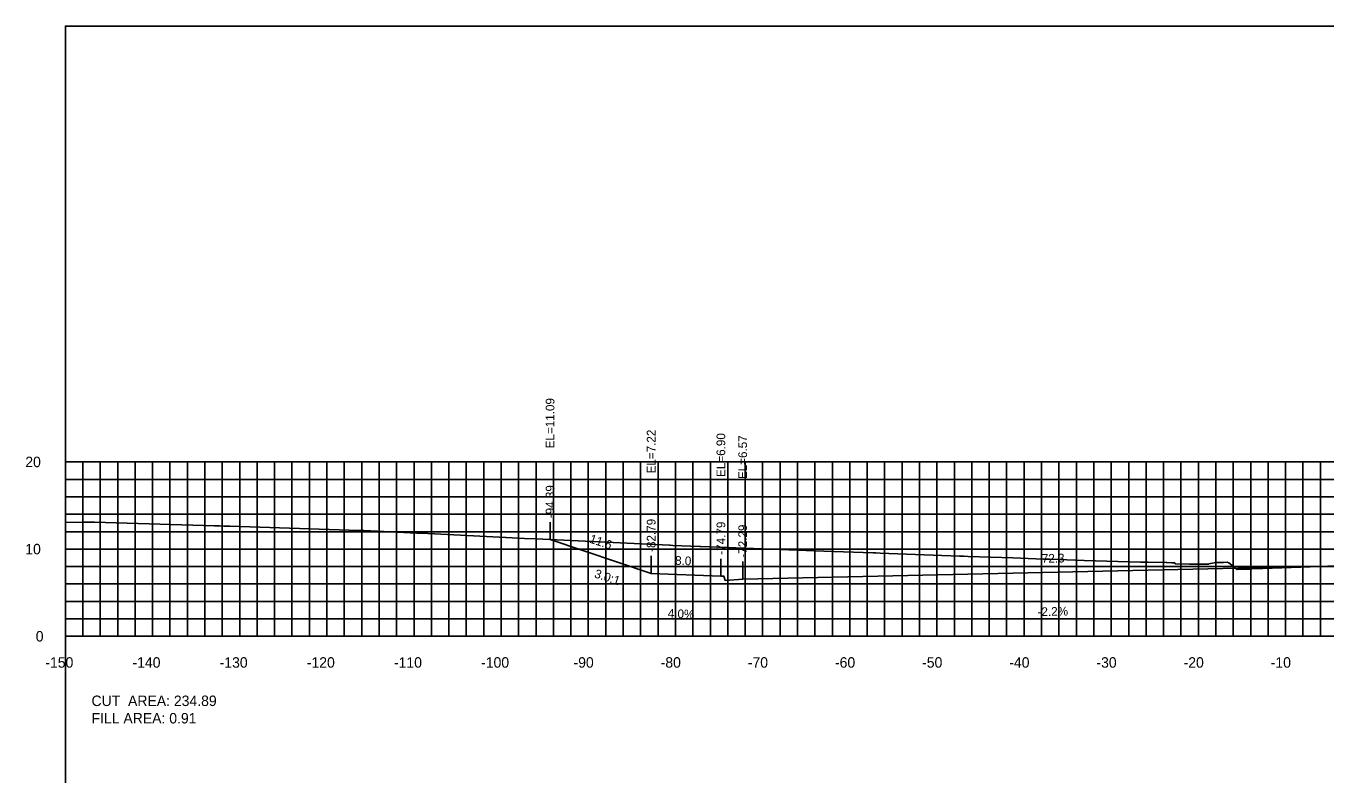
# Model space of a CAD drawing. Extents: x 1797419 to 1809236, y 248759 to 251512.
# Drawn here: x 1804856.5 to 1805005.6, y 250959 to 251044.9 of the extents above; entities that cross this region are included whole.
import ezdxf

# ---------------------------------------------------------------- set-up
doc = ezdxf.new("R2010")
doc.units = 0
for name, color, linetype in [('10', 7, 'Continuous'), ('3', 7, 'Continuous'), ('31', 7, 'Continuous'), ('4', 7, 'Continuous'), ('60', 7, 'Continuous'), ('ANNO-TXT', 7, 'Continuous'), ('CL-CNST', 7, 'Continuous'), ('Level 62', 7, 'Continuous'), ('M-ROADS', 7, 'Continuous')]:
    doc.layers.add(name, color=color, linetype=linetype)

msp = doc.modelspace()

# ---------------------------------------------------------------- linework, layer by layer
for p, q in [((1804916.61, 250985.98), (1804916.61, 250987.98)), ((1804928.21, 250982.11), (1804928.21, 250984.11)), ((1804936.21, 250981.79), (1804936.21, 250983.79)), ((1804938.71, 250981.46), (1804938.71, 250983.46))]:
    msp.add_line(p, q)
msp.add_lwpolyline([(1804861, 250854.89), (1805161, 250854.89), (1805161, 251044.89), (1804861, 251044.89)], close=True)
at = {"layer": '60'}
for p, q in [((1804860.94, 250994.89), (1804861, 250994.89)), ((1804861, 250974.89), (1804861, 250994.89)), ((1804860.94, 250984.89), (1804861, 250984.89)), ((1804860.94, 250974.89), (1804861, 250974.89)), ((1804861, 250974.89), (1805161, 250974.89)), ((1804861, 250974.83), (1804861, 250974.89)), ((1804871, 250974.83), (1804871, 250974.89)), ((1804881, 250974.83), (1804881, 250974.89)), ((1804891, 250974.83), (1804891, 250974.89)), ((1804901, 250974.83), (1804901, 250974.89)), ((1804911, 250974.83), (1804911, 250974.89)), ((1804921, 250974.83), (1804921, 250974.89)), ((1804931, 250974.83), (1804931, 250974.89)), ((1804941, 250974.83), (1804941, 250974.89)), ((1804951, 250974.83), (1804951, 250974.89)), ((1804961, 250974.83), (1804961, 250974.89)), ((1804971, 250974.83), (1804971, 250974.89)), ((1804981, 250974.83), (1804981, 250974.89)), ((1804991, 250974.83), (1804991, 250974.89)), ((1805001, 250974.83), (1805001, 250974.89))]:
    msp.add_line(p, q, dxfattribs=at)
at = {"layer": 'CL-CNST'}
msp.add_lwpolyline([(1804916.61, 250985.98), (1804928.21, 250982.11), (1804936.21, 250981.79), (1804936.54, 250981.79), (1804936.71, 250981.29), (1804938.71, 250981.46), (1805011, 250983.05), (1805081, 250981.53), (1805083, 250981.36), (1805083.17, 250981.86), (1805083.5, 250981.86), (1805085.5, 250981.94), (1805090.5, 250982.04), (1805091.5, 250982.08), (1805094.63, 250983.12)], dxfattribs=at)
at = {"layer": 'Level 62'}
for p, q in [((1804861, 250994.89), (1805161, 250994.89)), ((1804861, 250974.89), (1804861, 250994.89)), ((1804863, 250974.89), (1804863, 250994.89)), ((1804865, 250974.89), (1804865, 250994.89)), ((1804867, 250974.89), (1804867, 250994.89)), ((1804869, 250974.89), (1804869, 250994.89)), ((1804871, 250974.89), (1804871, 250994.89)), ((1804873, 250974.89), (1804873, 250994.89)), ((1804875, 250974.89), (1804875, 250994.89)), ((1804877, 250974.89), (1804877, 250994.89)), ((1804879, 250974.89), (1804879, 250994.89)), ((1804881, 250974.89), (1804881, 250994.89)), ((1804883, 250974.89), (1804883, 250994.89)), ((1804885, 250974.89), (1804885, 250994.89)), ((1804887, 250974.89), (1804887, 250994.89)), ((1804889, 250974.89), (1804889, 250994.89)), ((1804891, 250974.89), (1804891, 250994.89)), ((1804893, 250974.89), (1804893, 250994.89)), ((1804895, 250974.89), (1804895, 250994.89)), ((1804897, 250974.89), (1804897, 250994.89)), ((1804899, 250974.89), (1804899, 250994.89)), ((1804901, 250974.89), (1804901, 250994.89)), ((1804903, 250974.89), (1804903, 250994.89)), ((1804905, 250974.89), (1804905, 250994.89)), ((1804907, 250974.89), (1804907, 250994.89)), ((1804909, 250974.89), (1804909, 250994.89)), ((1804911, 250974.89), (1804911, 250994.89)), ((1804913, 250974.89), (1804913, 250994.89)), ((1804915, 250974.89), (1804915, 250994.89)), ((1804917, 250974.89), (1804917, 250994.89)), ((1804919, 250974.89), (1804919, 250994.89)), ((1804921, 250974.89), (1804921, 250994.89)), ((1804923, 250974.89), (1804923, 250994.89)), ((1804925, 250974.89), (1804925, 250994.89)), ((1804927, 250974.89), (1804927, 250994.89)), ((1804929, 250974.89), (1804929, 250994.89)), ((1804931, 250974.89), (1804931, 250994.89)), ((1804933, 250974.89), (1804933, 250994.89)), ((1804935, 250974.89), (1804935, 250994.89)), ((1804937, 250974.89), (1804937, 250994.89)), ((1804939, 250974.89), (1804939, 250994.89)), ((1804941, 250974.89), (1804941, 250994.89)), ((1804943, 250974.89), (1804943, 250994.89)), ((1804945, 250974.89), (1804945, 250994.89)), ((1804947, 250974.89), (1804947, 250994.89)), ((1804949, 250974.89), (1804949, 250994.89)), ((1804951, 250974.89), (1804951, 250994.89)), ((1804953, 250974.89), (1804953, 250994.89)), ((1804955, 250974.89), (1804955, 250994.89)), ((1804957, 250974.89), (1804957, 250994.89)), ((1804959, 250974.89), (1804959, 250994.89)), ((1804961, 250974.89), (1804961, 250994.89)), ((1804963, 250974.89), (1804963, 250994.89)), ((1804965, 250974.89), (1804965, 250994.89)), ((1804967, 250974.89), (1804967, 250994.89)), ((1804969, 250974.89), (1804969, 250994.89)), ((1804971, 250974.89), (1804971, 250994.89)), ((1804973, 250974.89), (1804973, 250994.89)), ((1804975, 250974.89), (1804975, 250994.89)), ((1804977, 250974.89), (1804977, 250994.89)), ((1804979, 250974.89), (1804979, 250994.89)), ((1804981, 250974.89), (1804981, 250994.89)), ((1804983, 250974.89), (1804983, 250994.89)), ((1804985, 250974.89), (1804985, 250994.89)), ((1804987, 250974.89), (1804987, 250994.89)), ((1804989, 250974.89), (1804989, 250994.89)), ((1804991, 250974.89), (1804991, 250994.89)), ((1804993, 250974.89), (1804993, 250994.89)), ((1804995, 250974.89), (1804995, 250994.89)), ((1804997, 250974.89), (1804997, 250994.89)), ((1804999, 250974.89), (1804999, 250994.89)), ((1805001, 250974.89), (1805001, 250994.89)), ((1805003, 250974.89), (1805003, 250994.89)), ((1805005, 250974.89), (1805005, 250994.89)), ((1804861, 250992.89), (1805161, 250992.89)), ((1804861, 250990.89), (1805161, 250990.89)), ((1804861, 250988.89), (1805161, 250988.89)), ((1804861, 250986.89), (1805161, 250986.89)), ((1804861, 250984.89), (1805161, 250984.89)), ((1804861, 250982.89), (1805161, 250982.89)), ((1804861, 250980.89), (1805161, 250980.89)), ((1804861, 250978.89), (1805161, 250978.89)), ((1804861, 250976.89), (1805161, 250976.89)), ((1804861, 250974.89), (1805161, 250974.89))]:
    msp.add_line(p, q, dxfattribs=at)
at = {"layer": 'M-ROADS'}
msp.add_lwpolyline([(1804861, 250987.94), (1804862.94, 250987.99), (1804863.07, 250987.99), (1804863.07, 250987.99), (1804863.08, 250987.99), (1804863.37, 250987.99), (1804863.42, 250987.99), (1804863.76, 250987.99), (1804864.1, 250987.98), (1804864.35, 250987.97), (1804878.12, 250987.57), (1804878.67, 250987.56), (1804878.68, 250987.56), (1804879.18, 250987.54), (1804879.83, 250987.52), (1804879.9, 250987.52), (1804894.66, 250987.02), (1804895.19, 250987.01), (1804895.26, 250987.01), (1804896.04, 250986.99), (1804901.32, 250986.73), (1804902.58, 250986.67), (1804903.36, 250986.64), (1804911.53, 250986.22), (1804911.59, 250986.22), (1804913.68, 250986.12), (1804914.99, 250986.05), (1804930.33, 250985.33), (1804930.38, 250985.33), (1804930.69, 250985.32), (1804933.79, 250985.18), (1804933.92, 250985.18), (1804948.01, 250984.67), (1804953.68, 250984.46), (1804953.98, 250984.45), (1804954.47, 250984.44), (1804963.6, 250984.08), (1804964.09, 250984.07), (1804964.57, 250984.06), (1804969.7, 250983.89), (1804973.23, 250983.73), (1804973.52, 250983.73), (1804973.92, 250983.72), (1804977.89, 250983.59), (1804984.34, 250983.41), (1804984.63, 250983.4), (1804985.22, 250983.4), (1804987.31, 250983.36), (1804987.36, 250983.36), (1804987.97, 250983.33), (1804988.29, 250983.32), (1804988.35, 250983.21), (1804989.98, 250983.18), (1804992.17, 250983.16), (1804992.21, 250983.2), (1804992.82, 250983.32), (1804993.08, 250983.35), (1804993.31, 250983.35), (1804993.43, 250983.35), (1804993.65, 250983.35), (1804993.79, 250983.35), (1804993.86, 250983.35), (1804994.3, 250983.39), (1804994.48, 250983.32), (1804994.83, 250983.06), (1804995.09, 250982.83), (1804995.43, 250982.56), (1804996.95, 250982.59), (1804996.99, 250982.6), (1804997.12, 250982.62), (1804997.13, 250982.62), (1804998.4, 250982.66), (1805009.31, 250983.03)], dxfattribs=at)

# ---------------------------------------------------------------- texts
msp.add_text('3.0:1', height=1, rotation=341.5651).set_placement((1804921.62, 250981.67))
at = {"layer": '10'}
for s, p in [('-150', (1804858.7, 250971.29)), ('-140', (1804868.7, 250971.29)), ('-130', (1804878.7, 250971.29)), ('-120', (1804888.7, 250971.29)), ('-110', (1804898.7, 250971.29)), ('-100', (1804908.7, 250971.29)), ('-90', (1804919.3, 250971.29)), ('-80', (1804929.3, 250971.29)), ('-70', (1804939.3, 250971.29)), ('-60', (1804949.3, 250971.29)), ('-50', (1804959.3, 250971.29)), ('-40', (1804969.3, 250971.29)), ('-30', (1804979.3, 250971.29)), ('-20', (1804989.3, 250971.29)), ('-10', (1804999.3, 250971.29))]:
    msp.add_text(s, height=1.2, dxfattribs=at).set_placement(p)
at = {"layer": '3'}
for s, p in [('EL=11.09', (1804917.11, 250996.45)), ('EL=7.22', (1804928.71, 250993.57)), ('EL=6.90', (1804936.71, 250993.17)), ('EL=6.57', (1804939.21, 250992.92)), ('-94.39', (1804917.11, 250988.43)), ('-82.79', (1804928.71, 250984.57)), ('-74.79', (1804936.71, 250984.25)), ('-72.29', (1804939.21, 250983.91))]:
    msp.add_text(s, height=1, rotation=90, dxfattribs=at).set_placement(p)
at = {"layer": '31'}
for s, p in [('20', (1804856.4, 250994.29)), ('10', (1804856.4, 250984.29)), ('0', (1804857.6, 250974.29))]:
    msp.add_text(s, height=1.2, dxfattribs=at).set_placement(p)
at = {"layer": '4'}
for s, rotation, p in [('11.6', 341.5651, (1804921.05, 250985.66)), ('8.0', 357.7094, (1804930.94, 250983.1)), ('72.3', 1.2603, (1804973.05, 250983.31)), ('4.0%', 357.7094, (1804930.1, 250977.03)), ('-2.2%', 1.2603, (1804972.56, 250977.2))]:
    msp.add_text(s, height=1, rotation=rotation, dxfattribs=at).set_placement(p)
at = {"layer": '60'}
msp.add_text('-', height=0.0001, dxfattribs=at).set_placement((1804861, 250974.89))
at = {"layer": 'ANNO-TXT'}
for s, p in [('CUT  AREA: 234.89', (1804864, 250966.89)), ('FILL AREA: 0.91', (1804864, 250964.89))]:
    msp.add_text(s, height=1.2, dxfattribs=at).set_placement(p)

doc.saveas('drawing.dxf')
